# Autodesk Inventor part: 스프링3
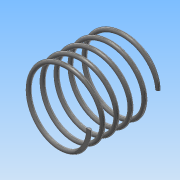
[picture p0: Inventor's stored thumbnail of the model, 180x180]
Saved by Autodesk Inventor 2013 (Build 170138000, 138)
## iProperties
Created: 2015-11
Part Number: 스프링3
Material: 강철, 탄소
Document SubType Name: Modeling
Designer: Administrator
Density: 7.87 g/cm^3
Mass: 1.53352 g
Surface Area: 7.86938 cm^2
Volume: 0.194856 cm^3
Author: Administrator
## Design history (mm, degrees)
sketch "스케치1"
  geometry: L1 (8, 16.67)-(0, 16.67); L2 (0, 16.67)-(0, 0); L3 (0, 0)-(8, 0); L4 (8, 0)-(8, 16.67); C1 r 0.5 at (8, 0)
  constraints: 8 end point, 2 parallel, 1 centre point, 1 coincident, 1 horizontal, 1 perpendicular
  dimensions: "d0" = 16 diameter of L4 L2; "d2" = 16.66987 distance between parallel lines of L3 L1 (derived); "d3" = 1 diameter of C1
feature "코일1" sketch "스케치1" pitch "d4" = 10; turns "d6" = 5; dims "d5" = 16.66987 (= d2), "d7" = 0, angle "d8" = 90 deg, angle "d9" = 90 deg, "d10" = 0, "d11" = 0
sketch "스케치2"
  geometry: L1 (0, 10)-(16.67, 10); L2 (16.67, 10)-(16.67, -10); L3 (16.67, -10)-(0, -10); L4 (0, -10)-(0, 10); 4 further points
  constraints: 8 end point, 2 coincident, 2 midpoint, 2 parallel, 1 horizontal, 1 perpendicular
  dimensions: "d12" = 20 distance between parallel lines of L3 L1
extrude "돌출1" sketch "스케치2" stored distance "d15" = 0; taper "d16" = 0 deg
node "솔리드1"
